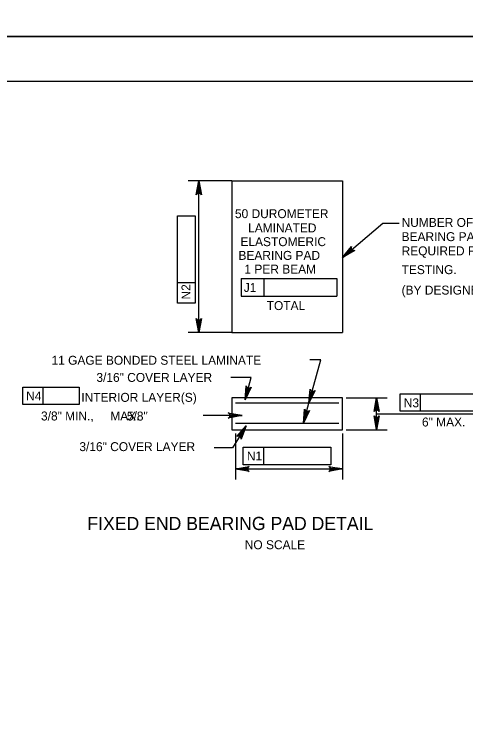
# Model space of a CAD drawing. Extents: x 638263 to 640391, y 293683 to 298655.
# Drawn here: x 639750.3 to 639902, y 297608 to 297849 of the extents above; entities that cross this region are included whole.
import ezdxf

# ---------------------------------------------------------------- set-up
doc = ezdxf.new("R2010")
doc.units = 0
for name, color, linetype in [('2', 7, 'Continuous'), ('3', 7, 'Continuous'), ('5', 7, 'Continuous'), ('6', 7, 'Continuous'), ('8', 7, 'Continuous'), ('PLT-BNDY', 7, 'Continuous')]:
    doc.layers.add(name, color=color, linetype=linetype)

msp = doc.modelspace()

# ---------------------------------------------------------------- linework, layer by layer
at = {"layer": '2'}
msp.add_line((639316.46, 297826.46), (640102.46, 297826.46), dxfattribs=at)
at = {"layer": '3'}
for p, q in [((639812.33, 297741.96), (639812.33, 297792.92)), ((639823.43, 297792.92), (639860.63, 297792.92)), ((639823.43, 297792.92), (639823.43, 297741.96)), ((639860.63, 297792.92), (639860.63, 297741.96)), ((639805.14, 297781.18), (639811.05, 297781.18)), ((639805.14, 297758.63), (639805.14, 297781.18)), ((639811.05, 297781.18), (639811.05, 297751.78)), ((639874.2, 297778.71), (639879.7, 297778.71)), ((639826.57, 297760.06), (639834.13, 297760.06)), ((639826.57, 297760.06), (639826.57, 297754.16)), ((639834.13, 297760.06), (639834.13, 297754.16)), ((639834.13, 297760.06), (639858.72, 297760.06)), ((639858.72, 297760.06), (639858.72, 297754.16)), ((639805.14, 297751.78), (639805.14, 297758.63)), ((639811.05, 297758.63), (639805.14, 297758.63)), ((639826.57, 297754.16), (639858.72, 297754.16)), ((639811.05, 297751.78), (639805.14, 297751.78)), ((639823.43, 297741.96), (639860.63, 297741.96)), ((639829.88, 297726.77), (639823.04, 297726.77)), ((639827.95, 297719.28), (639829.88, 297726.77)), ((639753.19, 297723.6), (639772.1, 297723.6)), ((639753.19, 297717.69), (639753.19, 297723.6)), ((639760.03, 297717.69), (639760.03, 297723.6)), ((639772.1, 297723.6), (639772.1, 297717.69)), ((639879.96, 297721.34), (639886.8, 297721.34)), ((639879.96, 297715.43), (639879.96, 297721.34)), ((639886.8, 297715.43), (639886.8, 297721.34)), ((639886.8, 297721.34), (639909.35, 297721.34)), ((639860.63, 297719.98), (639823.43, 297719.98)), ((639823.43, 297719.98), (639823.43, 297709.25)), ((639860.63, 297709.25), (639860.63, 297719.98)), ((639861.86, 297719.98), (639875.63, 297719.98)), ((639872.09, 297709.25), (639872.09, 297719.98)), ((639872.09, 297719.98), (639872.09, 297719.98)), ((639772.1, 297717.69), (639753.19, 297717.69)), ((639859.38, 297718.2), (639824.68, 297718.2)), ((639872.09, 297714.61), (639909.74, 297714.61)), ((639909.35, 297715.43), (639879.96, 297715.43)), ((639824.68, 297711.48), (639859.38, 297711.48)), ((639823.43, 297709.25), (639860.63, 297709.25)), ((639828.26, 297710.51), (639823.67, 297703.17)), ((639861.86, 297709.25), (639875.63, 297709.25)), ((639823.67, 297703.17), (639817.44, 297703.17)), ((639827.28, 297703.34), (639834.13, 297703.34)), ((639827.28, 297697.43), (639827.28, 297703.34)), ((639834.13, 297697.43), (639834.13, 297703.34)), ((639834.13, 297703.34), (639856.68, 297703.34)), ((639856.68, 297703.34), (639856.68, 297697.43)), ((639856.68, 297697.43), (639827.28, 297697.43))]:
    msp.add_line(p, q, dxfattribs=at)
for points in [[(639812.33, 297792.92), (639813.2, 297788.26), (639812.95, 297788.61), (639812.64, 297788.8), (639812.33, 297788.85), (639812.02, 297788.8), (639811.7, 297788.61), (639811.46, 297788.26), (639812.33, 297792.92), (639811.7, 297788.61), (639812.02, 297788.8), (639812.33, 297792.92), (639812.33, 297788.85), (639812.64, 297788.8), (639812.33, 297792.92), (639812.95, 297788.61)], [(639860.63, 297767.2), (639874.2, 297778.71)], [(639860.63, 297767.2), (639863.62, 297770.88), (639863.51, 297770.46), (639863.57, 297770.1), (639863.73, 297769.83), (639863.98, 297769.63), (639864.32, 297769.51), (639864.75, 297769.55), (639860.63, 297767.2), (639864.32, 297769.51), (639863.98, 297769.63), (639860.63, 297767.2), (639863.73, 297769.83), (639863.57, 297770.1), (639860.63, 297767.2), (639863.51, 297770.46)], [(639812.33, 297741.96), (639811.46, 297746.62), (639811.7, 297746.26), (639812.02, 297746.08), (639812.33, 297746.02), (639812.64, 297746.08), (639812.95, 297746.26), (639813.2, 297746.62), (639812.33, 297741.96), (639812.95, 297746.26), (639812.64, 297746.08), (639812.33, 297741.96), (639812.33, 297746.02), (639812.02, 297746.08), (639812.33, 297741.96), (639811.7, 297746.26)], [(639827.95, 297719.28), (639828.27, 297724.01), (639828.42, 297723.6), (639828.67, 297723.35), (639828.96, 297723.22), (639829.28, 297723.19), (639829.63, 297723.29), (639829.96, 297723.58), (639827.95, 297719.28), (639829.63, 297723.29), (639829.28, 297723.19), (639827.95, 297719.28), (639828.96, 297723.22), (639828.67, 297723.35), (639827.95, 297719.28), (639828.42, 297723.6)], [(639849.35, 297718.2), (639849.75, 297722.92), (639849.89, 297722.51), (639850.14, 297722.25), (639850.43, 297722.11), (639850.74, 297722.08), (639851.09, 297722.18), (639851.43, 297722.46), (639849.35, 297718.2), (639851.09, 297722.18), (639850.74, 297722.08), (639849.35, 297718.2), (639850.43, 297722.11), (639850.14, 297722.25), (639849.35, 297718.2), (639849.89, 297722.51)], [(639872.09, 297719.98), (639872.96, 297715.32), (639872.71, 297715.67), (639872.4, 297715.86), (639872.09, 297715.91), (639871.78, 297715.86), (639871.46, 297715.67), (639871.22, 297715.32), (639872.09, 297719.98), (639871.46, 297715.67), (639871.78, 297715.86), (639872.09, 297719.98), (639872.09, 297715.91), (639872.4, 297715.86), (639872.09, 297719.98), (639872.71, 297715.67)], [(639847.49, 297711.48), (639847.89, 297716.21), (639848.03, 297715.79), (639848.28, 297715.53), (639848.57, 297715.4), (639848.89, 297715.36), (639849.24, 297715.46), (639849.57, 297715.74), (639847.49, 297711.48), (639849.24, 297715.46), (639848.89, 297715.36), (639847.49, 297711.48), (639848.57, 297715.4), (639848.28, 297715.53), (639847.49, 297711.48), (639848.03, 297715.79)], [(639826.9, 297714.06), (639822.24, 297713.18), (639822.6, 297713.43), (639822.79, 297713.74), (639822.84, 297714.06), (639822.79, 297714.37), (639822.6, 297714.68), (639822.24, 297714.93), (639826.9, 297714.06), (639822.6, 297714.68), (639822.79, 297714.37), (639826.9, 297714.06), (639822.84, 297714.06), (639822.79, 297713.74), (639826.9, 297714.06), (639822.6, 297713.43)], [(639872.09, 297709.25), (639871.22, 297713.91), (639871.46, 297713.55), (639871.78, 297713.36), (639872.09, 297713.31), (639872.4, 297713.36), (639872.71, 297713.55), (639872.96, 297713.91), (639872.09, 297709.25), (639872.71, 297713.55), (639872.4, 297713.36), (639872.09, 297709.25), (639872.09, 297713.31), (639871.78, 297713.36), (639872.09, 297709.25), (639871.46, 297713.55)], [(639828.26, 297710.51), (639826.53, 297706.09), (639826.51, 297706.53), (639826.34, 297706.85), (639826.1, 297707.06), (639825.81, 297707.18), (639825.45, 297707.19), (639825.05, 297707.02), (639828.26, 297710.51), (639825.45, 297707.19), (639825.81, 297707.18), (639828.26, 297710.51), (639826.1, 297707.06), (639826.34, 297706.85), (639828.26, 297710.51), (639826.51, 297706.53)], [(639824.6, 297696.05), (639829.26, 297696.92), (639828.9, 297696.67), (639828.72, 297696.36), (639828.67, 297696.05), (639828.72, 297695.73), (639828.9, 297695.42), (639829.26, 297695.17), (639824.6, 297696.05), (639828.9, 297695.42), (639828.72, 297695.73), (639824.6, 297696.05), (639828.67, 297696.05), (639828.72, 297696.36), (639824.6, 297696.05), (639828.9, 297696.67)], [(639860.63, 297696.05), (639855.97, 297695.17), (639856.33, 297695.42), (639856.52, 297695.73), (639856.57, 297696.05), (639856.52, 297696.36), (639856.33, 297696.67), (639855.97, 297696.92), (639860.63, 297696.05), (639856.33, 297696.67), (639856.52, 297696.36), (639860.63, 297696.05), (639856.57, 297696.05), (639856.52, 297695.73), (639860.63, 297696.05), (639856.33, 297695.42)]]:
    msp.add_lwpolyline(points, dxfattribs=at)
at = {"layer": '5'}
for p, q in [((639847.53, 297711.64), (639853.36, 297732.71)), ((639826.91, 297714.06), (639813.83, 297714.06))]:
    msp.add_line(p, q, dxfattribs=at)
at = {"layer": '6'}
msp.add_line((639853.36, 297732.71), (639849.68, 297732.71), dxfattribs=at)
at = {"layer": '8'}
for p, q in [((639823.37, 297792.92), (639808.79, 297792.92)), ((639823.37, 297741.96), (639808.79, 297741.96)), ((639824.6, 297708.02), (639824.6, 297692.5)), ((639860.63, 297708.02), (639860.63, 297692.5)), ((639824.6, 297696.05), (639860.63, 297696.05))]:
    msp.add_line(p, q, dxfattribs=at)
for points in [[(639811.94, 297790.55), (639812.72, 297790.55), (639812.33, 297792.92)], [(639811.94, 297744.32), (639812.72, 297744.32), (639812.33, 297741.96)]]:
    msp.add_lwpolyline(points, close=True, dxfattribs=at)
at = {"layer": 'PLT-BNDY'}
for points in [[(639276.46, 298435.46), (640117.46, 298435.46), (640117.46, 297841.46), (639276.46, 297841.46)], [(639276.46, 297841.46), (640117.46, 297841.46), (640117.46, 297247.46), (639276.46, 297247.46)]]:
    msp.add_lwpolyline(points, close=True, dxfattribs=at)

# ---------------------------------------------------------------- texts
at = {"layer": '3'}
for s, height, p in [('50 DUROMETER', 3, (639824.47, 297780.41)), ('NUMBER OF', 3, (639880.47, 297777.46)), ('LAMINATED', 3, (639828.9, 297775.61)), ('ELASTOMERIC', 3, (639826.32, 297770.99)), ('BEARING PADS', 3, (639880.47, 297772.68)), ('BEARING PAD', 3, (639825.65, 297766.38)), ('REQUIRED FOR', 3, (639880.47, 297767.9)), ('1 PER BEAM', 3, (639827.65, 297761.76)), ('TESTING.', 3, (639880.47, 297761.58)), ('(BY DESIGNER)', 3, (639880.47, 297754.71)), ('TOTAL', 3, (639835.14, 297749.49)), ('11 GAGE BONDED STEEL LAMINATE', 3, (639762.83, 297731.1)), ('3/16" COVER LAYER', 3, (639777.92, 297725.33)), ('N4', 3, (639754.31, 297719.09)), ('INTERIOR LAYER(S)', 3, (639772.84, 297718.63)), ('N3', 3, (639881.21, 297716.78)), ('3/8" MIN.,     MAX.', 3, (639759.31, 297712.36)), (' 5/8"', 3, (639787.05, 297712.34)), ('6" MAX.', 3, (639887.32, 297710.34)), ('3/16" COVER LAYER', 3, (639772.2, 297702.05)), ('N1', 3, (639828.47, 297698.91)), ('FIXED END BEARING PAD DETAIL', 4.4292, (639774.87, 297675.5)), ('NO SCALE', 3, (639827.77, 297669.06))]:
    msp.add_text(s, height=height, dxfattribs=at).set_placement(p)
for s, rotation, p in [('N2', 90, (639809.51, 297753.05)), ('J1', 359.9382, (639827.44, 297755.61))]:
    msp.add_text(s, height=3, rotation=rotation, dxfattribs=at).set_placement(p)

doc.saveas('drawing.dxf')
